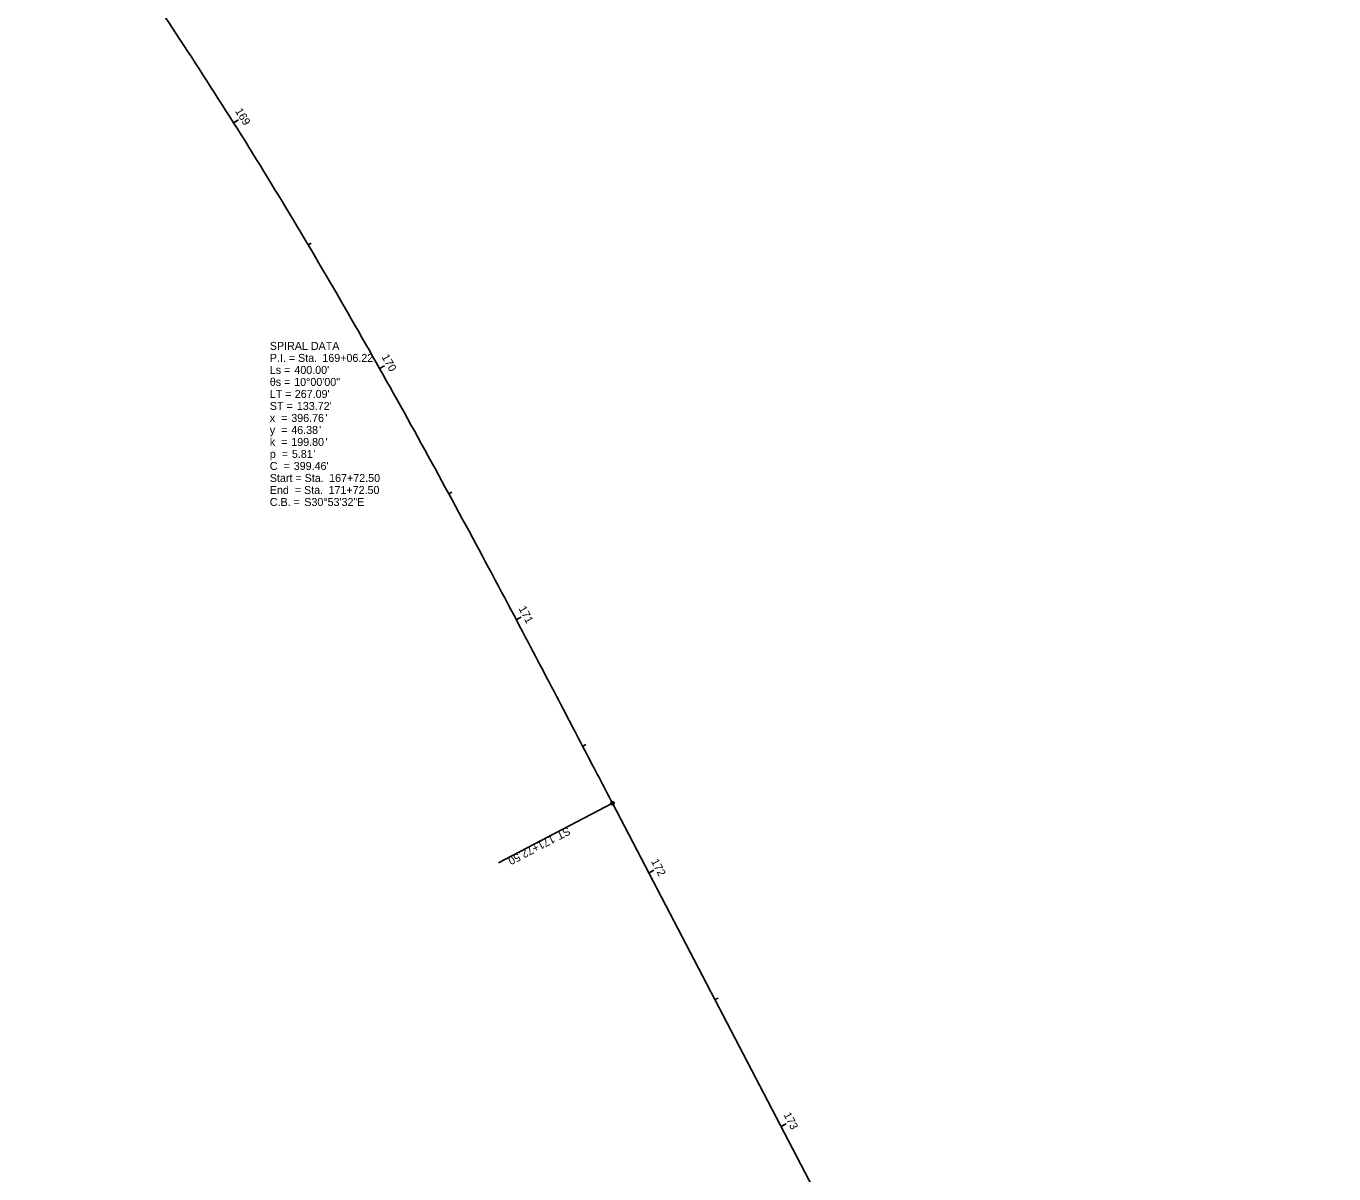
# Model space of a CAD drawing. Extents: x 2297881 to 2300632, y 559916 to 564460.
# Drawn here: x 2298181.2 to 2298638.6, y 563653.7 to 564055.2 of the extents above; entities that cross this region are included whole.
import ezdxf

# ---------------------------------------------------------------- set-up
doc = ezdxf.new("R2010")
doc.units = 0
for name, color, linetype in [('GE_X_Alignment', 7, 'Continuous'), ('GE_X_Alignment_1000_Cardinal_Points', 7, 'Continuous'), ('GE_X_Alignment_1000_Curve_Data', 7, 'Continuous'), ('GE_X_Alignment_1000_Stations', 7, 'Continuous'), ('GE_X_Alignment_100_Cardinal_Points', 7, 'Continuous'), ('GE_X_Alignment_100_Curve_Data', 7, 'Continuous'), ('GE_X_Alignment_100_Stations', 7, 'Continuous'), ('GE_X_Alignment_500_Cardinal_Points', 7, 'Continuous'), ('GE_X_Alignment_500_Curve_Data', 7, 'Continuous'), ('GE_X_Alignment_500_Stations', 7, 'Continuous')]:
    doc.layers.add(name, color=color, linetype=linetype)

msp = doc.modelspace()

# ---------------------------------------------------------------- linework, layer by layer
at = {"layer": 'GE_X_Alignment'}
msp.add_line((2298386.28, 563783.36), (2299396.64, 561847.4), dxfattribs=at)
msp.add_open_spline([(2298181.18, 564126.15), (2298185.25, 564120.86), (2298193.28, 564110.22), (2298209, 564088.68), (2298228.01, 564061.29), (2298249.89, 564027.8), (2298270.94, 563993.79), (2298291.28, 563959.34), (2298311.01, 563924.55), (2298330.26, 563889.48), (2298349.14, 563854.22), (2298364.66, 563824.72), (2298377.02, 563801.09), (2298383.19, 563789.27), (2298386.28, 563783.36)], degree=3, dxfattribs=at)
at = {"layer": 'GE_X_Alignment_1000_Cardinal_Points'}
msp.add_line((2298386.28, 563783.36), (2298346.38, 563762.54), dxfattribs=at)
msp.add_circle((2298386.28, 563783.36), 0.6, dxfattribs=at)
at = {"layer": 'GE_X_Alignment_1000_Stations'}
msp.add_line((2298304.82, 563935.4), (2298306.56, 563936.38), dxfattribs=at)
at = {"layer": 'GE_X_Alignment_100_Cardinal_Points'}
msp.add_line((2298386.28, 563783.36), (2298346.38, 563762.54), dxfattribs=at)
msp.add_circle((2298386.28, 563783.36), 0.6, dxfattribs=at)
at = {"layer": 'GE_X_Alignment_100_Stations'}
for p, q in [((2298253.76, 564021.37), (2298255.45, 564022.44)), ((2298279.81, 563978.7), (2298280.84, 563979.31)), ((2298304.82, 563935.4), (2298306.56, 563936.38)), ((2298329.01, 563891.64), (2298330.06, 563892.22)), ((2298352.61, 563847.56), (2298354.38, 563848.5)), ((2298375.86, 563803.3), (2298376.93, 563803.86)), ((2298399, 563758.98), (2298400.77, 563759.9)), ((2298422.13, 563714.65), (2298423.2, 563715.2)), ((2298445.27, 563670.32), (2298447.04, 563671.25))]:
    msp.add_line(p, q, dxfattribs=at)
at = {"layer": 'GE_X_Alignment_500_Cardinal_Points'}
msp.add_line((2298386.28, 563783.36), (2298346.38, 563762.54), dxfattribs=at)
msp.add_circle((2298386.28, 563783.36), 0.6, dxfattribs=at)
at = {"layer": 'GE_X_Alignment_500_Stations'}
for p, q in [((2298253.76, 564021.37), (2298254.78, 564022.01)), ((2298304.82, 563935.4), (2298306.56, 563936.38)), ((2298352.61, 563847.56), (2298353.67, 563848.13)), ((2298399, 563758.98), (2298400.06, 563759.53)), ((2298445.27, 563670.32), (2298446.33, 563670.88))]:
    msp.add_line(p, q, dxfattribs=at)

# ---------------------------------------------------------------- texts
at = {"layer": 'GE_X_Alignment_1000_Cardinal_Points'}
for s, p in [('ST', (2298370.66, 563775.15)), ('171+72.50', (2298365.26, 563772.34))]:
    msp.add_text(s, height=2.8, rotation=207.5598, dxfattribs=at).set_placement(p)
at = {"layer": 'GE_X_Alignment_1000_Curve_Data'}
for s, p in [('SPIRAL DATA', (2298266.42, 563941.94)), ('P.I. = Sta. ', (2298266.42, 563937.74)), ('169+06.22', (2298284.79, 563937.74)), ('Ls = ', (2298266.42, 563933.54)), ("400.00'", (2298275.01, 563933.54)), ('θs = ', (2298266.42, 563929.34)), ('10°00\'00"', (2298274.95, 563929.34)), ('LT = ', (2298266.42, 563925.14)), ("267.09'", (2298275.15, 563925.14)), ('ST = ', (2298266.42, 563920.94)), ("133.72'", (2298275.88, 563920.94)), ('x  = ', (2298266.42, 563916.74)), ('396.76', (2298273.92, 563916.74)), ("'", (2298285.88, 563916.74)), ('y  = ', (2298266.42, 563912.54)), ('46.38', (2298273.92, 563912.54)), ("'", (2298283.7, 563912.54)), ('k  = ', (2298266.42, 563908.34)), ('199.80', (2298273.92, 563908.34)), ("'", (2298285.88, 563908.34)), ('p  = ', (2298266.42, 563904.14)), ('5.81', (2298274.14, 563904.14)), ("'", (2298281.75, 563904.14)), ('Start = Sta. ', (2298266.42, 563895.74)), ('C  = ', (2298266.42, 563899.94)), ("399.46'", (2298274.79, 563899.94)), ('167+72.50', (2298287.18, 563895.74)), ('End  = Sta. ', (2298266.42, 563891.54)), ('171+72.50', (2298286.96, 563891.54)), ('C.B. = ', (2298266.42, 563887.34)), ('S30°53\'32"E', (2298278.48, 563887.34))]:
    msp.add_text(s, height=2.8, dxfattribs=at).set_placement(p)
at = {"layer": 'GE_X_Alignment_1000_Stations'}
msp.add_text('170', height=2.8, rotation=299.4195, dxfattribs=at).set_placement((2298305.43, 563939.51))
at = {"layer": 'GE_X_Alignment_100_Cardinal_Points'}
for s, p in [('ST', (2298370.66, 563775.15)), ('171+72.50', (2298365.26, 563772.34))]:
    msp.add_text(s, height=2.8, rotation=207.5598, dxfattribs=at).set_placement(p)
at = {"layer": 'GE_X_Alignment_100_Curve_Data'}
for s, p in [('SPIRAL DATA', (2298266.42, 563941.94)), ('P.I. = Sta. ', (2298266.42, 563937.74)), ('169+06.22', (2298284.79, 563937.74)), ('Ls = ', (2298266.42, 563933.54)), ("400.00'", (2298275.01, 563933.54)), ('θs = ', (2298266.42, 563929.34)), ('10°00\'00"', (2298274.95, 563929.34)), ('LT = ', (2298266.42, 563925.14)), ("267.09'", (2298275.15, 563925.14)), ('ST = ', (2298266.42, 563920.94)), ("133.72'", (2298275.88, 563920.94)), ('x  = ', (2298266.42, 563916.74)), ('396.76', (2298273.92, 563916.74)), ("'", (2298285.88, 563916.74)), ('y  = ', (2298266.42, 563912.54)), ('46.38', (2298273.92, 563912.54)), ("'", (2298283.7, 563912.54)), ('k  = ', (2298266.42, 563908.34)), ('199.80', (2298273.92, 563908.34)), ("'", (2298285.88, 563908.34)), ('p  = ', (2298266.42, 563904.14)), ('5.81', (2298274.14, 563904.14)), ("'", (2298281.75, 563904.14)), ('Start = Sta. ', (2298266.42, 563895.74)), ('C  = ', (2298266.42, 563899.94)), ("399.46'", (2298274.79, 563899.94)), ('167+72.50', (2298287.18, 563895.74)), ('End  = Sta. ', (2298266.42, 563891.54)), ('171+72.50', (2298286.96, 563891.54)), ('C.B. = ', (2298266.42, 563887.34)), ('S30°53\'32"E', (2298278.48, 563887.34))]:
    msp.add_text(s, height=2.8, dxfattribs=at).set_placement(p)
at = {"layer": 'GE_X_Alignment_100_Stations'}
for s, rotation, p in [('169', 302.2007, (2298254.18, 564025.48)), ('170', 299.4195, (2298305.43, 563939.51)), ('171', 297.8883, (2298353.36, 563851.48)), ('172', 297.5598, (2298399.7, 563763.04)), ('173', 297.5598, (2298446.02, 563674.4))]:
    msp.add_text(s, height=2.8, rotation=rotation, dxfattribs=at).set_placement(p)
at = {"layer": 'GE_X_Alignment_500_Cardinal_Points'}
for s, p in [('ST', (2298370.66, 563775.15)), ('171+72.50', (2298365.26, 563772.34))]:
    msp.add_text(s, height=2.8, rotation=207.5598, dxfattribs=at).set_placement(p)
at = {"layer": 'GE_X_Alignment_500_Curve_Data'}
for s, p in [('SPIRAL DATA', (2298266.42, 563941.94)), ('P.I. = Sta. ', (2298266.42, 563937.74)), ('169+06.22', (2298284.79, 563937.74)), ('Ls = ', (2298266.42, 563933.54)), ("400.00'", (2298275.01, 563933.54)), ('θs = ', (2298266.42, 563929.34)), ('10°00\'00"', (2298274.95, 563929.34)), ('LT = ', (2298266.42, 563925.14)), ("267.09'", (2298275.15, 563925.14)), ('ST = ', (2298266.42, 563920.94)), ("133.72'", (2298275.88, 563920.94)), ('x  = ', (2298266.42, 563916.74)), ('396.76', (2298273.92, 563916.74)), ("'", (2298285.88, 563916.74)), ('y  = ', (2298266.42, 563912.54)), ('46.38', (2298273.92, 563912.54)), ("'", (2298283.7, 563912.54)), ('k  = ', (2298266.42, 563908.34)), ('199.80', (2298273.92, 563908.34)), ("'", (2298285.88, 563908.34)), ('p  = ', (2298266.42, 563904.14)), ('5.81', (2298274.14, 563904.14)), ("'", (2298281.75, 563904.14)), ('Start = Sta. ', (2298266.42, 563895.74)), ('C  = ', (2298266.42, 563899.94)), ("399.46'", (2298274.79, 563899.94)), ('167+72.50', (2298287.18, 563895.74)), ('End  = Sta. ', (2298266.42, 563891.54)), ('171+72.50', (2298286.96, 563891.54)), ('C.B. = ', (2298266.42, 563887.34)), ('S30°53\'32"E', (2298278.48, 563887.34))]:
    msp.add_text(s, height=2.8, dxfattribs=at).set_placement(p)
at = {"layer": 'GE_X_Alignment_500_Stations'}
msp.add_text('170', height=2.8, rotation=299.4195, dxfattribs=at).set_placement((2298305.43, 563939.51))

doc.saveas('drawing.dxf')
